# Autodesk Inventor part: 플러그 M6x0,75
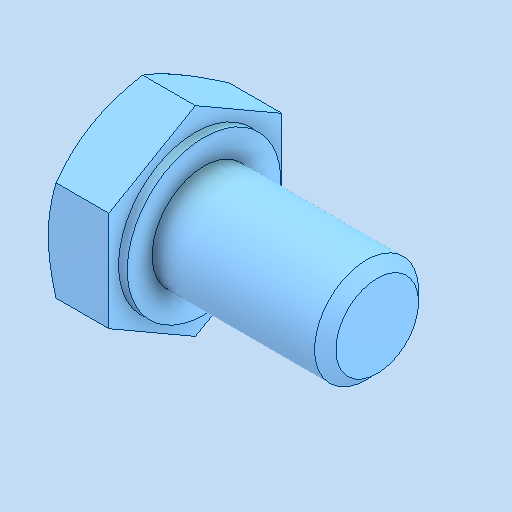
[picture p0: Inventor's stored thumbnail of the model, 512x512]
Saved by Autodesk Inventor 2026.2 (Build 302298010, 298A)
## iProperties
Created: 2026-03
Part Number: 플러그 M6x0,75
Material: 강철, 연강
Description: 6각 머리 볼트 및 6각 머리 나사
Document SubType Name: Modeling
Designer: PC-2-06
Density: 7.85 g/cm^3
Appearance: 기본값
Author: jhkim
Sending System: Autodesk Inventor 2026
Preprocessor: ST-DEVELOPER v20.1
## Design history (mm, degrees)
feature "Solid1"
node "솔리드1"
